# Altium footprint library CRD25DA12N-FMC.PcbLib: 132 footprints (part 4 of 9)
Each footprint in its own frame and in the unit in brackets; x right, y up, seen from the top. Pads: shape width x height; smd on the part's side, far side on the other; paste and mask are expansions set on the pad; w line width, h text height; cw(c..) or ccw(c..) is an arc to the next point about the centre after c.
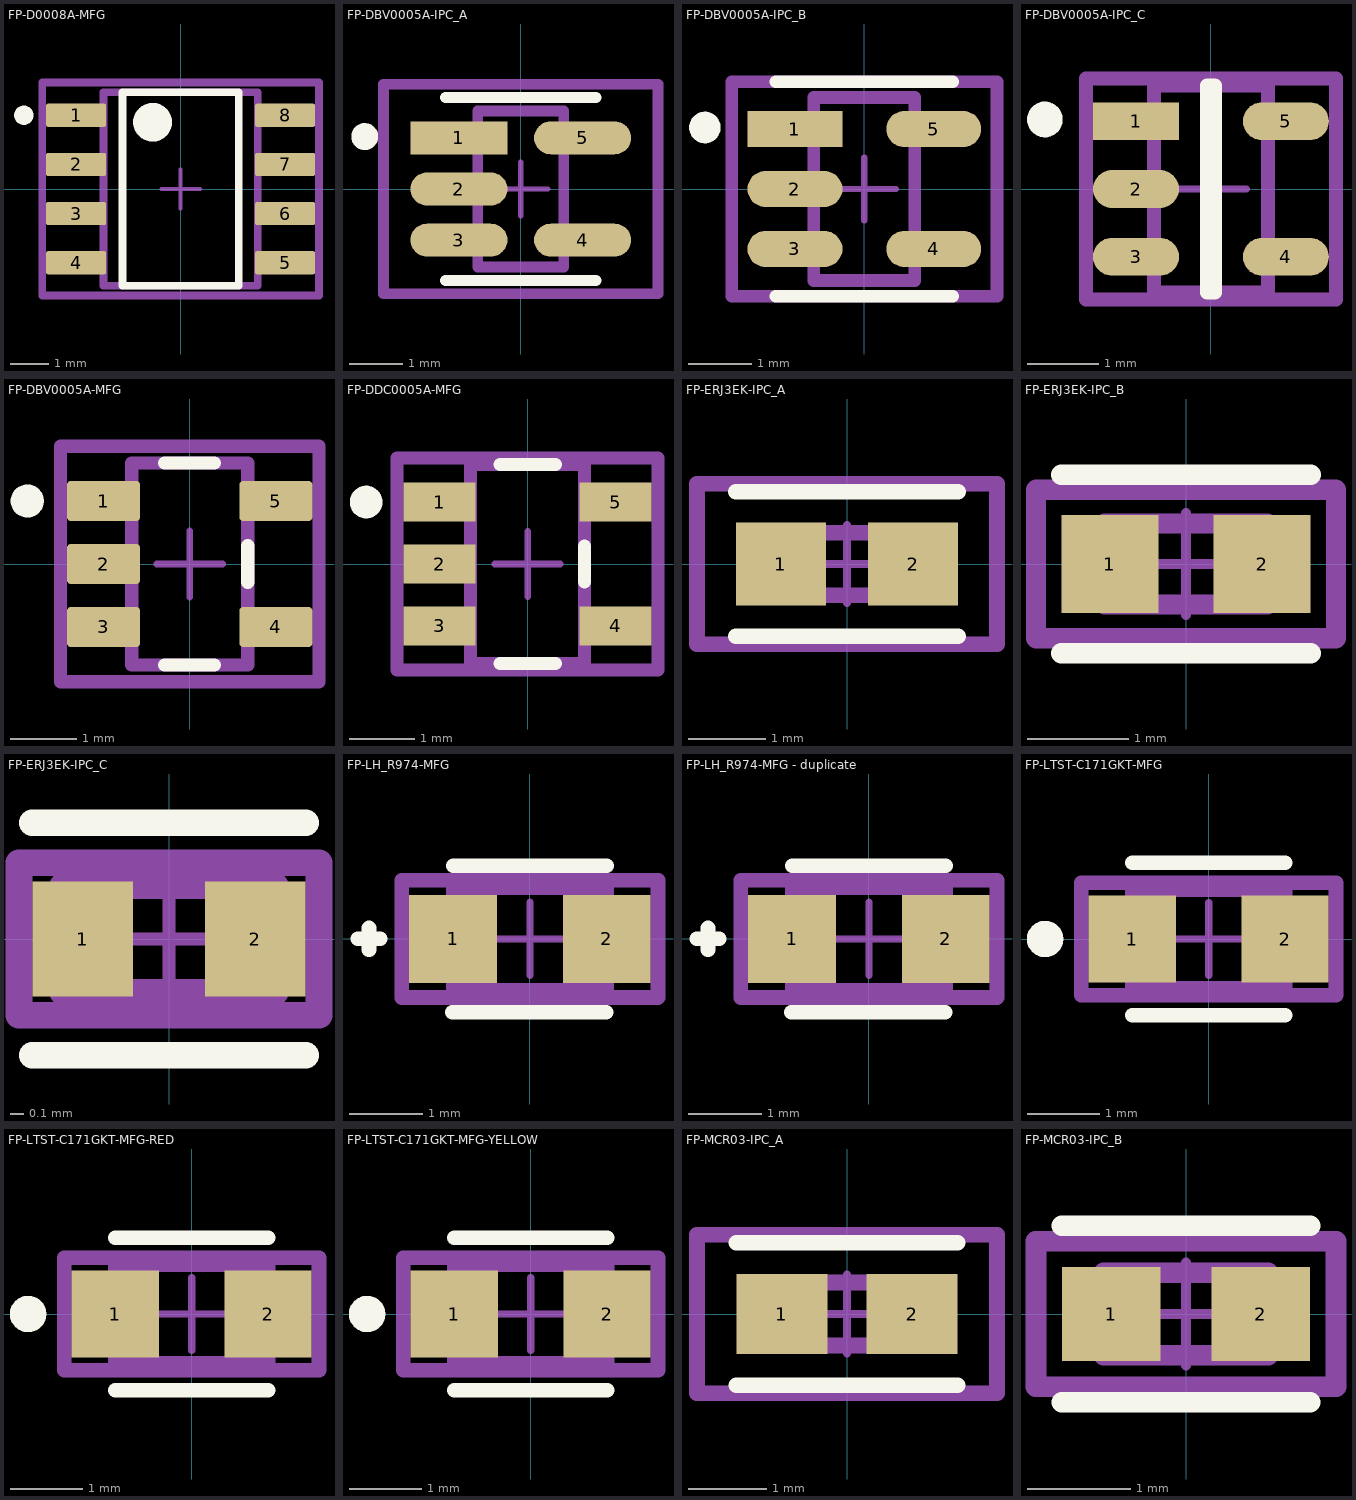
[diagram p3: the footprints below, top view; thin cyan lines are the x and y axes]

## FP-D0008A-MFG [mm]
pads (8):
  rrect17% 1.55x0.6 smd paste+0 mask+0: 1(-2.7,1.905) 2(-2.7,0.635) 3(-2.7,-0.635) 4(-2.7,-1.905) 5(2.7,-1.905) 6(2.7,-0.635) 7(2.7,0.635) 8(2.7,1.905)
Top Overlay:
  circle w0.5: c-0.725,1.725 r0.25
  circle w0.25: c-4.05,1.905 r0.125
  lines w0.2: -1.5,-2.5 -1.5,2.5 1.5,2.5 1.5,-2.5 -1.5,-2.5
Mechanical 5:
  lines w0.2: -3.575,-2.75 -3.575,2.75 3.575,2.75 3.575,-2.75 -3.575,-2.75
  text ".Designator" at 0,0.188 h1
Mechanical 13:
  lines w0.2: -1.99,-2.5 -1.99,2.5 1.99,2.5 1.99,-2.5 -1.99,-2.5
Mechanical 15:
  lines w0.2: -3.575,-2.75 -3.575,2.75 3.575,2.75 3.575,-2.75 -3.575,-2.75
Mechanical 16:
  lines w0.1: -0.5,0 0.5,0 ; 0,-0.5 0,0.5
3D body "IC_Texas_Instruments_ISO7220ADR_eec.STEP": height 0.25, standoff 0, extent -3.575,-2.75 3.575,2.75

## FP-DBV0005A-IPC_A [mm]
pads (5):
  rect 1.805x0.612 smd paste+0 mask+0: 1(-1.15,0.95)
  rrect100% 1.805x0.612 smd paste+0 mask+0: 2(-1.15,0) 3(-1.15,-0.95) 4(1.15,-0.95) 5(1.15,0.95)
Top Overlay:
  circle w0.25: c-2.903,0.975 r0.125
  lines w0.2: -1.4,-1.7 1.4,-1.7 ; -1.4,1.7 1.4,1.7
Mechanical 5:
  lines w0.2: -2.553,-1.95 -2.553,1.95 2.553,1.95 2.553,-1.95 -2.553,-1.95
  text ".Designator" at 0,0 h1
Mechanical 13:
  lines w0.2: -0.8,-1.45 -0.8,1.45 0.8,1.45 0.8,-1.45 -0.8,-1.45
Mechanical 15:
  lines w0.2: -2.553,-1.95 -2.553,1.95 2.553,1.95 2.553,-1.95 -2.553,-1.95
Mechanical 16:
  lines w0.1: -0.5,0 0.5,0 ; 0,-0.5 0,0.5
3D body "IC_Texas_Instruments_SN74AHC1G00DBVR_eec.STEP": height 0.25, standoff 0, extent -2.553,-1.95 2.553,1.95

## FP-DBV0005A-IPC_B [mm]
pads (5):
  rect 1.505x0.572 smd paste+0 mask+0: 1(-1.1,0.95)
  rrect100% 1.505x0.572 smd paste+0 mask+0: 2(-1.1,0) 3(-1.1,-0.95) 4(1.1,-0.95) 5(1.1,0.95)
Top Overlay:
  circle w0.25: c-2.528,0.975 r0.125
  lines w0.2: -1.4,-1.7 1.4,-1.7 ; -1.4,1.7 1.4,1.7
Mechanical 5:
  lines w0.2: -2.103,-1.7 2.103,-1.7 2.103,1.7 -2.103,1.7 -2.103,-1.7
  text ".Designator" at 0,0 h1
Mechanical 13:
  lines w0.2: -0.8,-1.45 0.8,-1.45 0.8,1.45 -0.8,1.45 -0.8,-1.45
Mechanical 15:
  lines w0.2: -2.103,-1.7 2.103,-1.7 2.103,1.7 -2.103,1.7 -2.103,-1.7
Mechanical 16:
  lines w0.1: -0.5,0 0.5,0 ; 0,-0.5 0,0.5
3D body "IC_Texas_Instruments_SN74AHC1G00DBVR_eec.STEP": height 0.25, standoff 0, extent -2.103,-1.7 2.103,1.7

## FP-DBV0005A-IPC_C [mm]
pads (5):
  rect 1.205x0.532 smd paste+0 mask+0: 1(-1.05,0.95)
  rrect100% 1.205x0.532 smd paste+0 mask+0: 2(-1.05,0) 3(-1.05,-0.95) 4(1.05,-0.95) 5(1.05,0.95)
Top Overlay:
  circle w0.25: c-2.328,0.975 r0.125
  lines w0.2: -0.052,-1.45 -0.052,1.45 0.052,1.45 0.052,-1.45 -0.052,-1.45
Mechanical 5:
  lines w0.2: -1.753,-1.55 1.753,-1.55 1.753,1.55 -1.753,1.55 -1.753,-1.55
  text ".Designator" at 0,0.188 h1
Mechanical 13:
  lines w0.2: -0.8,-1.45 0.8,-1.45 0.8,1.45 -0.8,1.45 -0.8,-1.45
Mechanical 15:
  lines w0.2: -1.753,-1.55 1.753,-1.55 1.753,1.55 -1.753,1.55 -1.753,-1.55
Mechanical 16:
  lines w0.1: -0.5,0 0.5,0 ; 0,-0.5 0,0.5
3D body "IC_Texas_Instruments_SN74AHC1G00DBVR_eec.STEP": height 0.25, standoff 0, extent -1.753,-1.55 1.753,1.55

## FP-DBV0005A-MFG [mm]
pads (5):
  rrect17% 1.1x0.6 smd paste+0 mask+0: 1(-1.3,0.95) 2(-1.3,0) 3(-1.3,-0.95) 4(1.3,-0.95) 5(1.3,0.95)
Top Overlay:
  circle w0.25: c-2.45,0.95 r0.125
  lines w0.2: -0.375,-1.525 0.375,-1.525 ; -0.375,1.525 0.375,1.525 ; 0.875,-0.275 0.875,0.275
Mechanical 5:
  lines w0.2: -1.95,-1.775 1.95,-1.775 1.95,1.775 -1.95,1.775 -1.95,-1.775
  text ".Designator" at 0,0 h1
Mechanical 13:
  lines w0.2: -0.875,-1.525 0.875,-1.525 0.875,1.525 -0.875,1.525 -0.875,-1.525
Mechanical 15:
  lines w0.2: -1.95,-1.775 1.95,-1.775 1.95,1.775 -1.95,1.775 -1.95,-1.775
Mechanical 16:
  lines w0.1: -0.5,0 0.5,0 ; 0,-0.5 0,0.5
3D body "IC_Texas_Instruments_SN65LVDT2DBVT_eec.STEP": height 0.25, standoff 0, extent -1.95,-1.775 1.95,1.775

## FP-DDC0005A-MFG [mm]
pads (5):
  rect 1.1x0.6 smd paste+0 mask+0: 1(-1.35,0.95) 2(-1.35,0) 3(-1.35,-0.95) 4(1.35,-0.95) 5(1.35,0.95)
Top Overlay:
  circle w0.25: c-2.475,0.95 r0.125
  lines w0.2: -0.425,-1.525 0.425,-1.525 ; -0.425,1.525 0.425,1.525 ; 0.875,-0.275 0.875,0.275
Mechanical 5:
  lines w0.2: -2,-1.625 -2,1.625 2,1.625 2,-1.625 -2,-1.625
  text ".Designator" at 0,0 h1
Mechanical 13:
  lines w0.2: -0.875,-1.525 -0.875,1.525 0.875,1.525 0.875,-1.525 -0.875,-1.525
Mechanical 15:
  lines w0.2: -2,-1.625 -2,1.625 2,1.625 2,-1.625 -2,-1.625
Mechanical 16:
  lines w0.1: -0.5,0 0.5,0 ; 0,-0.5 0,0.5
3D body "IC_Texas_Instruments_TPS62561DDCT_eec.STEP": height 0.25, standoff 0, extent -2,-1.625 2,1.625

## FP-ERJ3EK-IPC_A [mil]
pads (2):
  rect 45.53x41.82 smd paste+0 mask+0: 1(-33.5,0) 2(33.5,0)
Top Overlay:
  lines w7.87: -56.26,-36.66 56.26,-36.66 ; -56.26,36.66 56.26,36.66
Mechanical 5:
  lines w7.87: -75.95,-40.59 75.95,-40.59 75.95,40.59 -75.95,40.59 -75.95,-40.59
  text ".Designator" at 0,7.4 h39.37
Mechanical 13:
  lines w7.87: -31.5,-15.75 31.5,-15.75 31.5,15.75 -31.5,15.75 -31.5,-15.75
Mechanical 15:
  lines w7.87: -75.95,-40.59 75.95,-40.59 75.95,40.59 -75.95,40.59 -75.95,-40.59
Mechanical 16:
  lines w3.94: -19.68,0 19.68,0 ; 0,-19.68 0,19.68
3D body "Res_Panasonic_ERJ-3EKF12R0V_eec.STEP": height 10, standoff 0, extent -75.95,-40.59 75.95,40.59

## FP-ERJ3EK-IPC_B [mm]
pads (2):
  rect 0.957x0.962 smd paste+0 mask+0: 1(-0.751,0) 2(0.751,0)
Top Overlay:
  lines w0.2: -1.229,-0.881 1.229,-0.881 ; -1.229,0.881 1.229,0.881
Mechanical 5:
  lines w0.2: -1.479,-0.731 1.479,-0.731 1.479,0.731 -1.479,0.731 -1.479,-0.731
  text ".Designator" at 0,0.188 h1
Mechanical 13:
  lines w0.2: -0.8,-0.4 0.8,-0.4 0.8,0.4 -0.8,0.4 -0.8,-0.4
Mechanical 15:
  lines w0.2: -1.479,-0.731 1.479,-0.731 1.479,0.731 -1.479,0.731 -1.479,-0.731
Mechanical 16:
  lines w0.1: -0.5,0 0.5,0 ; 0,-0.5 0,0.5
3D body "Res_Panasonic_ERJ-3EKF12R0V_eec.STEP": height 0.25, standoff 0, extent -1.479,-0.731 1.479,0.731

## FP-ERJ3EK-IPC_C [mm]
pads (2):
  rect 0.757x0.862 smd paste+0 mask+0: 1(-0.651,0) 2(0.651,0)
Top Overlay:
  lines w0.2: -1.029,-0.875 1.029,-0.875 ; -1.029,0.875 1.029,0.875
Mechanical 5:
  lines w0.2: -1.129,-0.575 1.129,-0.575 1.129,0.575 -1.129,0.575 -1.129,-0.575
  text ".Designator" at 0,0.188 h1
Mechanical 13:
  lines w0.2: -0.8,-0.4 0.8,-0.4 0.8,0.4 -0.8,0.4 -0.8,-0.4
Mechanical 15:
  lines w0.2: -1.129,-0.575 1.129,-0.575 1.129,0.575 -1.129,0.575 -1.129,-0.575
Mechanical 16:
  lines w0.1: -0.5,0 0.5,0 ; 0,-0.5 0,0.5
3D body "Res_Panasonic_ERJ-3EKF12R0V_eec.STEP": height 0.25, standoff 0, extent -1.129,-0.575 1.129,0.575

## FP-LH_R974-MFG [mm]
pads (2):
  rect 1.2x1.2 smd paste+0 mask+0: 1(-1.05,0) 2(1.05,0)
Top Overlay:
  lines w0.2: -2.35,0 -2.05,0 ; -2.2,-0.15 -2.2,0.15 ; -1.061,-1.002 1.039,-1.002 ; -1.05,1 1.05,1
Mechanical 5:
  lines w0.2: -1.75,-0.8 1.75,-0.8 1.75,0.8 -1.75,0.8 -1.75,-0.8
  text ".Designator" at 0,0 h1
Mechanical 13:
  lines w0.2: -1.05,-0.7 1.05,-0.7 1.05,0.7 -1.05,0.7 -1.05,-0.7
Mechanical 15:
  lines w0.2: -1.75,-0.8 1.75,-0.8 1.75,0.8 -1.75,0.8 -1.75,-0.8
Mechanical 16:
  lines w0.1: -0.5,0 0.5,0 ; 0,-0.5 0,0.5
3D body "Diode_OSRAM_LH_R974-LP-1_eec.STEP": height 0.25, standoff 0, extent -1.75,-0.8 1.75,0.8

## FP-LH_R974-MFG - duplicate [mm]
pads (2):
  rect 1.2x1.2 smd paste+0 mask+0: 1(-1.05,0) 2(1.05,0)
Top Overlay:
  lines w0.2: -2.35,0 -2.05,0 ; -2.2,-0.15 -2.2,0.15 ; -1.061,-1.002 1.039,-1.002 ; -1.05,1 1.05,1
Mechanical 5:
  lines w0.2: -1.75,-0.8 1.75,-0.8 1.75,0.8 -1.75,0.8 -1.75,-0.8
  text ".Designator" at 0,0 h1
Mechanical 13:
  lines w0.2: -1.05,-0.7 1.05,-0.7 1.05,0.7 -1.05,0.7 -1.05,-0.7
Mechanical 15:
  lines w0.2: -1.75,-0.8 1.75,-0.8 1.75,0.8 -1.75,0.8 -1.75,-0.8
Mechanical 16:
  lines w0.1: -0.5,0 0.5,0 ; 0,-0.5 0,0.5
3D body "Diode_OSRAM_LH_R974-LP-1_eec.STEP": height 0.25, standoff 0, extent -1.75,-0.8 1.75,0.8

## FP-LTST-C171GKT-MFG [mm]
pads (2):
  rect 1.2x1.2 smd paste+0 mask+0: 1(-1.05,0) 2(1.05,0)
Top Overlay:
  circle w0.25: c-2.25,0 r0.125
  lines w0.2: -1.05,-1.05 1.05,-1.05 ; -1.05,1.05 1.05,1.05
Mechanical 5:
  lines w0.2: -1.75,-0.775 -1.75,0.775 1.75,0.775 1.75,-0.775 -1.75,-0.775
  text ".Designator" at 0,0 h1
Mechanical 13:
  lines w0.2: -1.05,-0.675 -1.05,0.675 1.05,0.675 1.05,-0.675 -1.05,-0.675
Mechanical 15:
  lines w0.2: -1.75,-0.775 -1.75,0.775 1.75,0.775 1.75,-0.775 -1.75,-0.775
Mechanical 16:
  lines w0.1: -0.5,0 0.5,0 ; 0,-0.5 0,0.5
3D body "Diode_Lite-On_LTST-C171GKT_eec.STEP": height 0.25, standoff 0, extent -1.75,-0.775 1.75,0.775

## FP-LTST-C171GKT-MFG-RED [mm]
pads (2):
  rect 1.2x1.2 smd paste+0 mask+0: 1(-1.05,0) 2(1.05,0)
Top Overlay:
  circle w0.25: c-2.25,0 r0.125
  lines w0.2: -1.05,-1.05 1.05,-1.05 ; -1.05,1.05 1.05,1.05
Mechanical 5:
  lines w0.2: -1.75,-0.775 -1.75,0.775 1.75,0.775 1.75,-0.775 -1.75,-0.775
  text ".Designator" at 0,0 h1
Mechanical 13:
  lines w0.2: -1.05,-0.675 -1.05,0.675 1.05,0.675 1.05,-0.675 -1.05,-0.675
Mechanical 15:
  lines w0.2: -1.75,-0.775 -1.75,0.775 1.75,0.775 1.75,-0.775 -1.75,-0.775
Mechanical 16:
  lines w0.1: -0.5,0 0.5,0 ; 0,-0.5 0,0.5
3D body "LED 0805 - RED.STEP": height 0.8, standoff 0, extent -1,-0.625 1,0.625

## FP-LTST-C171GKT-MFG-YELLOW [mm]
pads (2):
  rect 1.2x1.2 smd paste+0 mask+0: 1(-1.05,0) 2(1.05,0)
Top Overlay:
  circle w0.25: c-2.25,0 r0.125
  lines w0.2: -1.05,-1.05 1.05,-1.05 ; -1.05,1.05 1.05,1.05
Mechanical 5:
  lines w0.2: -1.75,-0.775 1.75,-0.775 1.75,0.775 -1.75,0.775 -1.75,-0.775
  text ".Designator" at 0,0 h1
Mechanical 13:
  lines w0.2: -1.05,-0.675 1.05,-0.675 1.05,0.675 -1.05,0.675 -1.05,-0.675
Mechanical 15:
  lines w0.2: -1.75,-0.775 1.75,-0.775 1.75,0.775 -1.75,0.775 -1.75,-0.775
Mechanical 16:
  lines w0.1: -0.5,0 0.5,0 ; 0,-0.5 0,0.5
3D body "LED 0805 - YELLOW.STEP": height 0.8, standoff 0, extent -1,-0.625 1,0.625

## FP-MCR03-IPC_A [mm]
pads (2):
  rect 1.158x1.012 smd paste+0 mask+0: 1(-0.827,0) 2(0.827,0)
Top Overlay:
  lines w0.2: -1.406,-0.906 1.406,-0.906 ; -1.406,0.906 1.406,0.906
Mechanical 5:
  lines w0.2: -1.906,-1.006 -1.906,1.006 1.906,1.006 1.906,-1.006 -1.906,-1.006
  text ".Designator" at 0,0.188 h1
Mechanical 13:
  lines w0.2: -0.8,-0.4 -0.8,0.4 0.8,0.4 0.8,-0.4 -0.8,-0.4
Mechanical 15:
  lines w0.2: -1.906,-1.006 -1.906,1.006 1.906,1.006 1.906,-1.006 -1.906,-1.006
Mechanical 16:
  lines w0.1: -0.5,0 0.5,0 ; 0,-0.5 0,0.5
3D body "Res_Rohm_MCR03ERTF1182_eec.STEP": height 0.25, standoff 0, extent -1.906,-1.006 1.906,1.006

## FP-MCR03-IPC_B [mm]
pads (2):
  rect 0.958x0.912 smd paste+0 mask+0: 1(-0.727,0) 2(0.727,0)
Top Overlay:
  lines w0.2: -1.206,-0.856 1.206,-0.856 ; -1.206,0.856 1.206,0.856
Mechanical 5:
  lines w0.2: -1.456,-0.706 1.456,-0.706 1.456,0.706 -1.456,0.706 -1.456,-0.706
  text ".Designator" at 0,0.188 h1
Mechanical 13:
  lines w0.2: -0.8,-0.4 0.8,-0.4 0.8,0.4 -0.8,0.4 -0.8,-0.4
Mechanical 15:
  lines w0.2: -1.456,-0.706 1.456,-0.706 1.456,0.706 -1.456,0.706 -1.456,-0.706
Mechanical 16:
  lines w0.1: -0.5,0 0.5,0 ; 0,-0.5 0,0.5
3D body "Res_Rohm_MCR03ERTF1182_eec.STEP": height 0.25, standoff 0, extent -1.456,-0.706 1.456,0.706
